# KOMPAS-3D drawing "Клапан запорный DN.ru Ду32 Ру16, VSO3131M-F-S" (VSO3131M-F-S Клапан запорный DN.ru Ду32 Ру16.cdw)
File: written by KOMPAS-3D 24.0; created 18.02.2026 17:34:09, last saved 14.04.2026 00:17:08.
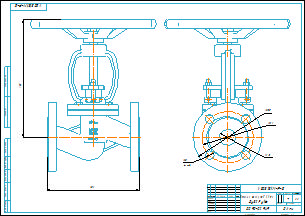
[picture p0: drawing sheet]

Document properties: Автор: R2D2; Форматы листов документа: A2; Полное имя файла: VSO3131M-F-S Клапан запорный DN.ru Ду32 Ру16.m3d; Масса: 7; Наименование: Клапан запорный DN.ru Ду32 Ру16; Количество листов документа: 1; Примечание: D090-02949

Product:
- Part/product: Клапан запорный DN.ru Ду32 Ру16  | designation VSO3131M-F-S
    Масса: 7
    Раздел спецификации: Прочие изделия
    Примечание: D090-02949

Views: Проекционный вид 2
Referenced files in E:\Работа\Зайцев\VSO3131M-F-S Клапан запорный DN.ru Ду15-100 Ру40\DN32\: VSO3131M-F-S Клапан запорный DN.ru Ду32 Ру40.m3d
Referenced files in E:\Работа\Зайцев\Для компаса\: чертеж DN.ru А3.cdt
Referenced files in E:\Работа\Зайцев\VSO3131M-F-S Клапан запорный DN.ru Ду15-100 Ру16\DN32\: VSO3131M-F-S Клапан запорный DN.ru Ду32 Ру16.m3d
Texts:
  VSO3131M-F-S
  чертеж DN.ru А3.cdt
  Клапан запорный DN.ru
  Ду32 Ру16
  Клапан запорный DN.ru Ду32 Ру16
  VSO3131M-F-S Клапан запорный DN.ru Ду32 Ру16
Dimensions and other numbers on the sheet: 0; 3; 5; 4; 135; 100; 32; 18; 4 отв.; 1:1; 1; 7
